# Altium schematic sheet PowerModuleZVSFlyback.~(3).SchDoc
size 431 x 279 mm; Date: Not shown in title block; ApprovedBy: Not shown in title block; CheckedBy: Not shown in title block; Author: Not shown in title block; CompanyName: Not shown in title block; Engineer: Not shown in title block; Organization: Not shown in title block; Address1: Not shown in title block; Address2: Not shown in title block; Address3: Not shown in title block; Address4: Not shown in title block; DocumentNumber: 1; Revision: Use project parameter SCH_Rev; SheetNumber: 3; SheetTotal: 3; PageSetup: Record=PageOptions¦CenterHorizontal=True¦CenterVertical=True¦PrintScale=1.00¦XCorrection=1.00¦YCorrection=1.00¦PrintKind=0¦BorderSize=5000000¦LeftOffset=0¦BottomOffset=0¦Orientation=2¦PaperLength=1000¦PaperWidth=1000¦Scale=100¦PaperSource=15¦PrintQuality=600¦MediaType=1¦DitherType=10¦PaperKind=Letter¦PrintScaleMode=1
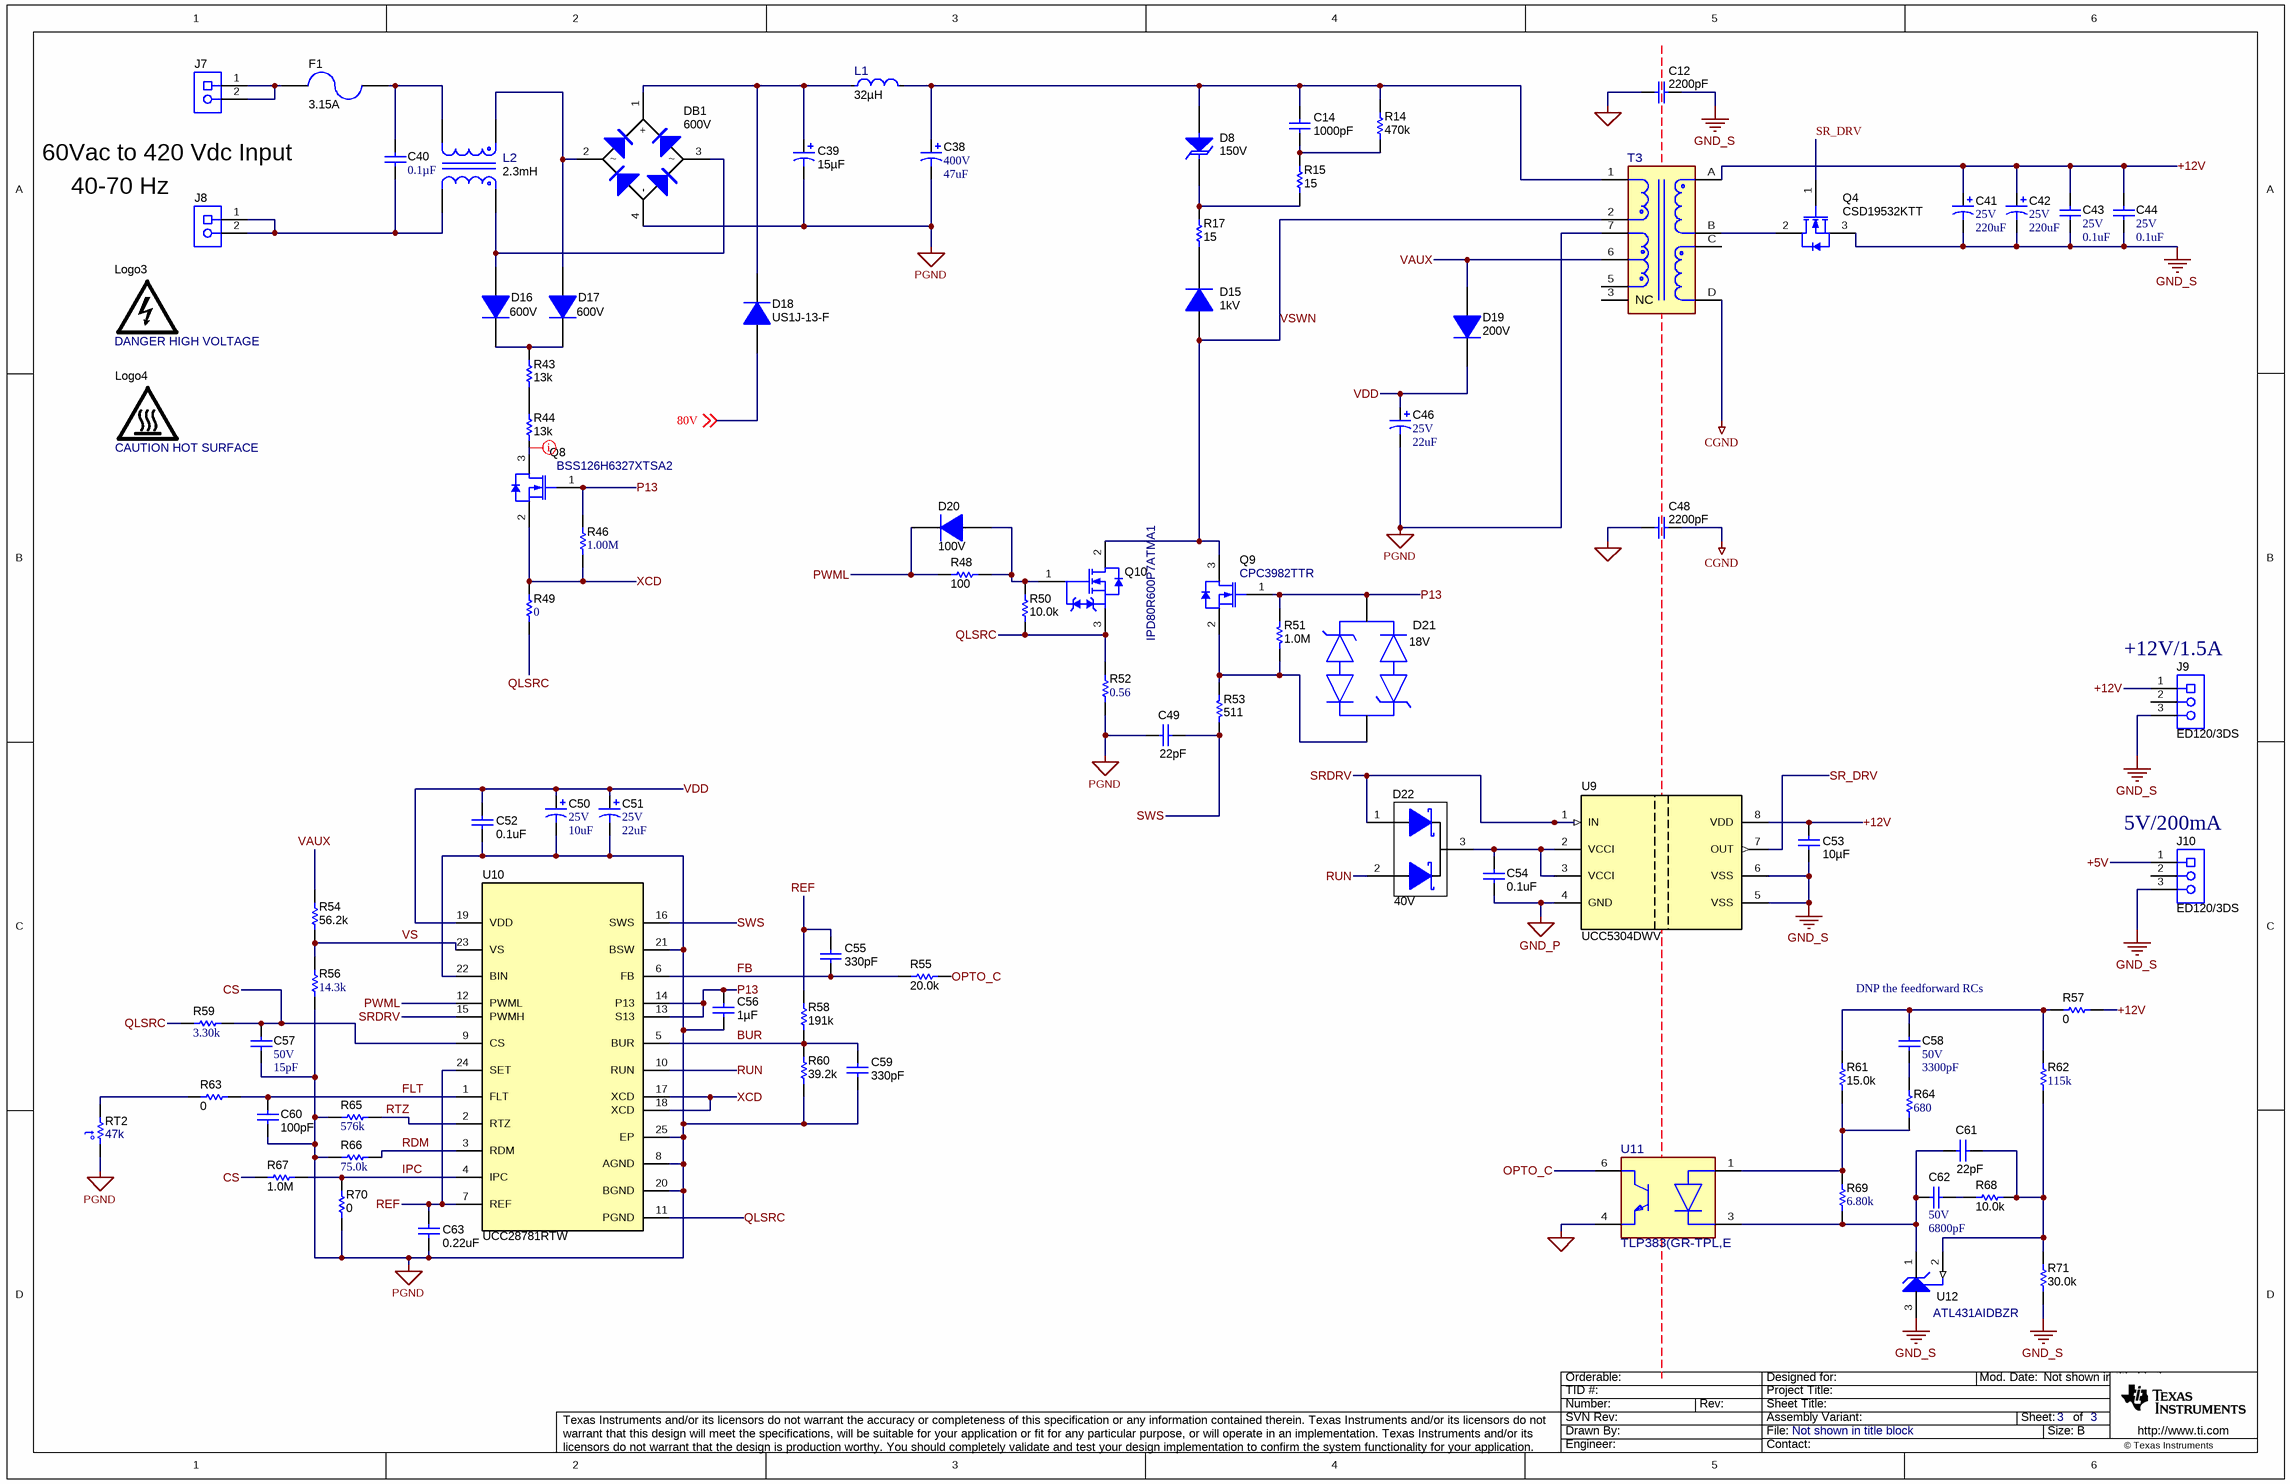
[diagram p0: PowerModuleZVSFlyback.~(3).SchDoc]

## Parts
C12  ValueDisplayed: 2200pF  [C900_9x13]  (hidden comment: C921U222MVVDBA7317)
C14  ValueDisplayed: 1000pF  [1206L]  (hidden comment: GRM31BR72J102KW01L)
C38  VDC_V: 400V  ValueDisplayed: 47uF  [CAPPR7.5-16x25]  (hidden comment: UCS2G470MHD)
C39  ValueDisplayed: 15µF  [UVC_1000x1600]  (hidden comment: UVC2G150MPD)
C40  ValueDisplayed: 0.1µF  [B32933_600x1500x2650]  (hidden comment: B32933A3104K000)
C41  VDC_V: 25V  ValueDisplayed: 220uF  [BT_1000x1250]  (hidden comment: UBT1E221MPD1TD)
C42  VDC_V: 25V  ValueDisplayed: 220uF  [BT_1000x1250]  (hidden comment: UBT1E221MPD1TD)
C43  VDC_V: 25V  ValueDisplayed: 0.1uF  [0603]  (hidden comment: 06033D104KAT2A)
C44  VDC_V: 25V  ValueDisplayed: 0.1uF  [0603]  (hidden comment: 06033D104KAT2A)
C46  VDC_V: 25V  ValueDisplayed: 22uF  [SM_RADIAL_D]  (hidden comment: EEE-FC1E220P)
C48  ValueDisplayed: 2200pF  [C900_9x13]  (hidden comment: C921U222MVVDBA7317)
C49  ValueDisplayed: 22pF  [0402S]  (hidden comment: GCM1555C1H220JA16D)
C50  VDC_V: 25V  ValueDisplayed: 10uF  [CAPSMT_62_D55]  (hidden comment: EMVA250ADA100MD55G)
C51  VDC_V: 25V  ValueDisplayed: 22uF  [SM_RADIAL_D]  (hidden comment: EEE-FC1E220P)
C52  ValueDisplayed: 0.1uF  [0402S]  (hidden comment: GRM155R71H104ME14D)
C53  ValueDisplayed: 10µF  [1206_180L]  (hidden comment: C1206C106J3RACAUTO)
C54  ValueDisplayed: 0.1uF  [0402S]  (hidden comment: GRM155R71H104ME14D)
C55  ValueDisplayed: 330pF  [0402S]  (hidden comment: GRM155R71H331KA01D)
C56  Cap_F: 1µF  [0603S]  (hidden comment: CGA3E1X7R1V105K080AC)
C57  VDC_V: 50V  ValueDisplayed: 15pF  [0402]  (hidden comment: CC0402JRNPO9BN150)
C58  VDC_V: 50V  ValueDisplayed: 3300pF  [0402]  (hidden comment: GRM155R71H332KA01D)
C59  ValueDisplayed: 330pF  [0402S]  (hidden comment: GRM155R71H331KA01D)
C60  ValueDisplayed: 100pF  [0402S]  (hidden comment: GRM1555C1H101JA01D)
C61  ValueDisplayed: 22pF  [0402S]  (hidden comment: GCM1555C1H220JA16D)
C62  VDC_V: 50V  ValueDisplayed: 6800pF  [0402]  (hidden comment: GRM155R71H682KA88D)
C63  ValueDisplayed: 0.22uF  [0402S]  (hidden comment: GRM155R71C224KA12D)
D8  VRWM: 150V  [SMA]  (hidden comment: SMAJ150A)
D15  Vr_V: 1kV  [SMA]  (hidden comment: MRA4007T3G)
D16  Vr_V: 600V  [TUMD2SM]  (hidden comment: RFU02VSM6STR)
D17  Vr_V: 600V  [TUMD2SM]  (hidden comment: RFU02VSM6STR)
D18  US1J-13-F  [SMA]
D19  Vr_V: 200V  [SOD-123H]  (hidden comment: CSFMT104-HF)
D20  Vr_V: 100V  [SOD-323]  (hidden comment: BAS316,115)
D21  CDSOD323-T18C  [FP-CDSOD323-T18C_SOD323-MFG]  (value not drawn)
D22  Vr_V: 40V  [SOT-323]  (hidden comment: BAS40W-05-7-F)
DB1  value 600V  [Z4-D]  (hidden comment: Z4DGP406L-HF)
F1  Irating_A: 3.15A  [FUSE_392]  (hidden comment: 39213150000)
J7  ED120/2DS  [On-Shore_ED120_2DS]  (value not drawn)
J8  ED120/2DS  [On-Shore_ED120_2DS]  (value not drawn)
J9  ED120/3DS  [On-Shore_ED120_3DS]
J10  ED120/3DS  [On-Shore_ED120_3DS]
L1  Ind_H: 32µH  [FP-7447052_PTH_D10MM0-MFG]  (hidden comment: 7447052)
L2  Ind_H: 2.3mH  [FP-RLTI-1387_PTH_CMC_0IN38_0IN60-MFG]  (hidden comment: RLTI-1387)
Logo3  DANGER HIGH VOLTAGE  [IEC_HighVoltage_Small]  (no BOM)
Logo4  CAUTION HOT SURFACE  [IEC_HotSurface_Small]  (no BOM)
Q4  CSD19532KTT  [KTT0002A]
Q8  BSS126H6327XTSA2  [SOT-23L]
Q9  CPC3982TTR  [SOT-23L]
Q10  IPD80R600P7ATMA1  [DPAK]
R14  ValueDisplayed: 470k  [0805_HV1]  (hidden comment: CRCW0805470KJNEA)
R15  ValueDisplayed: 15  [0805_HV1]  (hidden comment: CRCW080515R0JNEA)
R17  ValueDisplayed: 15  [0805_HV1]  (hidden comment: CRCW080515R0JNEA)
R43  ValueDisplayed: 13k  [1206L]  (hidden comment: CRCW120613K0JNEA)
R44  ValueDisplayed: 13k  [1206L]  (hidden comment: CRCW120613K0JNEA)
R46  ValueDisplayed: 1.00M  [0603]  (hidden comment: MCT06030C1004FP500)
R48  ValueDisplayed: 100  [0805_HV1]  (hidden comment: CRCW0805100RJNEA)
R49  ValueDisplayed: 0  [0603]  (hidden comment: RC0603JR-070RL)
R50  ValueDisplayed: 10.0k  [0402S]  (hidden comment: CRCW040210K0FKED)
R51  ValueDisplayed: 1.0M  [0402S]  (hidden comment: CRCW04021M00JNED)
R52  ValueDisplayed: 0.56  [1206]  (hidden comment: ERJ-8RQFR56V)
R53  ValueDisplayed: 511  [0402S]  (hidden comment: CRCW0402511RFKED)
R54  ValueDisplayed: 56.2k  [0402S]  (hidden comment: CRCW040256K2FKED)
R55  ValueDisplayed: 20.0k  [0402S]  (hidden comment: CRCW040220K0FKED)
R56  ValueDisplayed: 14.3k  [0402]  (hidden comment: CRCW040214K3FKED)
R57  ValueDisplayed: 0  [0402S]  (hidden comment: RC0402JR-070RL)
R58  ValueDisplayed: 191k  [0402S]  (hidden comment: CRCW0402191KFKED)
R59  ValueDisplayed: 3.30k  [0402]  (hidden comment: RK73H1ETTP3301F)
R60  ValueDisplayed: 39.2k  [0402S]  (hidden comment: CRCW040239K2FKED)
R61  ValueDisplayed: 15.0k  [0402S]  (hidden comment: CRCW040215K0FKED)
R62  ValueDisplayed: 115k  [0402]  (hidden comment: RC1005F1153CS)
R63  ValueDisplayed: 0  [0402S]  (hidden comment: CRCW04020000Z0EDHP)
R64  ValueDisplayed: 680  [0603]  (hidden comment: RC0603FR-07680RL)
R65  ValueDisplayed: 576k  [0402]  (hidden comment: CRCW0402576KFKED)
R66  ValueDisplayed: 75.0k  [0402]  (hidden comment: CRCW040275K0FKED)
R67  ValueDisplayed: 1.0M  [0402S]  (hidden comment: CRCW04021M00JNED)
R68  ValueDisplayed: 10.0k  [0402S]  (hidden comment: CRCW040210K0FKED)
R69  ValueDisplayed: 6.80k  [0603]  (hidden comment: RC0603FR-076K8L)
R70  ValueDisplayed: 0  [0402S]  (hidden comment: CRCW04020000Z0EDHP)
R71  ValueDisplayed: 30.0k  [0402S]  (hidden comment: CRCW040230K0FKED)
RT2  value 47k  [0603S]  (hidden comment: NCP18WB473J03RB)
T3  RLTI-1324  [FP-RLTI-1324_PTH_0IN980_0IN766-MFG]  (value not drawn)
U9  UCC5304DWV  [DWV0008A]
U10  UCC28781RTW  [RTW0024B]
U11  TLP383(GR-TPL,E  [FP-TLP383(GR-TPL,E_SO6-4-MFG]
U12  ATL431AIDBZR  [DBZ0003A_L]

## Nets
CGND: C48.1 T3.D
GND2: C12.2 C48.2 U11.4(Emitter)
GND_P: C54.2 U9.4(GND)
GND_S: C12.1 C41.2(-) C42.2(-) C43.2 C44.2 C53.2 J9.3 J10.3 Q4.3(S) R71.2 U9.5(VSS) U9.6(VSS) U12.3(ANODE)
PGND: C38.2(-) C39.2(-) C46.2(-) C49.1 C50.2(-) C51.2(-) C52.2 C56.2 C57.2 C59.2 C60.1 C63.2 DB1.4(-) R52.1 R56.1 R60.2 R65.1 R66.1 R70.1 RT2.2 T3.7 U10.8(AGND) U10.20(BGND) U10.21(BSW) U10.22(BIN) U10.25(EP)
80V: D18.2(A) ; off-sheet 80V
+5V: J10.1
+12V: C41.1(+) C42.1(+) C43.1 C44.1 C53.1 J9.1 R57.1 T3.A U9.8(VDD)
BUR: C59.1 R58.2 R60.1 U10.5(BUR)
CS: C57.1 R59.2 R67.2 U10.9(CS)
FB: C55.2 R55.1 U10.6(FB)
FLT: C60.2 R63.2 U10.1(FLT)
IPC: R67.1 R70.2 U10.4(IPC)
OPTO_C: R55.2 U11.6(Collector)
P13: C56.1 D21.2 Q8.1(G) Q9.1(G) R46.2 R51.2 U10.13(S13) U10.14(P13)
PWML: D20.1(K) R48.1 U10.12(PWML)
QLSRC: Q10.3(S) R49.1 R50.1 R52.2 R59.1 U10.11(PGND)
RDM: R66.2 U10.3(RDM)
REF: C55.1 C63.1 R58.1 U10.7(REF) U10.24(SET)
RTZ: R65.2 U10.2(RTZ)
RUN: D22.2(A) U10.10(RUN)
SR_DRV: Q4.1(G) U9.7(OUT)
SRDRV: D22.1(A) U9.1(IN) U10.15(PWMH)
SWS: C49.2 R53.1 U10.16(SWS)
VAUX: D19.2(A) R54.1 T3.6
VDD: C46.1(+) C50.1(+) C51.1(+) C52.1 D19.1(K) U10.19(VDD)
VS: R54.2 R56.2 U10.23(VS)
VSWN: D15.2(A) Q9.3(D) Q10.2(D) T3.2
XCD: Q8.2(S) R46.1 R49.2 U10.17(XCD) U10.18(XCD)
NetC14_1: C14.1 C38.1(+) D8.2(A) L1.2 R14.2 T3.1
NetC14_2: C14.2 R14.1 R15.2
NetC39_1: C39.1(+) D18.1(K) DB1.1(+) L1.1
NetC40_1: C40.1 F1.1 L2.3
NetC40_2: C40.2 J8.1 J8.2 L2.2
NetC54_1: C54.1 D22.3(K) U9.2(VCCI) U9.3(VCCI)
NetC58_1: C58.1 R57.2 R61.2 R62.2
NetC58_2: C58.2 R64.2
NetC61_1: C61.1 C62.2 R69.1 U11.3(Cathode) U12.1(CATHODE)
NetC61_2: C61.2 R62.1 R68.2 R71.1 U12.2(REF)
NetC62_1: C62.1 R68.1
NetD8_1: D8.1(K) R15.1 R17.2
NetD15_1: D15.1(K) R17.1
NetD16_1: D16.1(K) D17.1(K) R43.1
NetD16_2: D16.2(A) DB1.3 L2.1
NetD17_2: D17.2(A) DB1.2 L2.4
NetD20_2: D20.2(A) Q10.1(G) R48.2 R50.2
NetD21_1: D21.1 Q9.2(S) R51.1 R53.2
NetF1_2: F1.2 J7.1 J7.2
NetQ4_2: Q4.2(D) T3.B
NetQ8_3: Q8.3(D) R44.2
NetR43_2: R43.2 R44.1
NetR61_1: R61.1 R64.1 R69.2 U11.1(Anode)
NetR63_1: R63.1 RT2.1

Not connected (* = marked no-connect by the designer): J9 2; J10 2; T3 3(NC) 5 C

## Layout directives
net class HV: NetQ8_3

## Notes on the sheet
- 60Vac to 420 Vdc Input
- 40-70 Hz
- (near D21) 18V
- (near J9) +12V/1.5A
- (near J10) 5V/200mA
- (near C58) DNP the feedforward RCs

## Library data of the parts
C12 C48 = CMP-0078358-1: CAP, CERM, 2200 pF, X1 400 VAC/Y1 400 VAC, +/- 20%, Y5V, D9xL13mm; Manufacturer: Kemet; Cap_F: 2.2nF; SizeAreaWB_mm2: 121; VAC_X: 400V; SizeArea_mm2: 81; AEC Qualified: N; AEC Category: Q200; Value: 2200pF; TaMax_C: 125°C; SizeZ_mm: 13; TaMin_C: -40°C; SizeY_mm: 9; U/M: EA; AC_Safety: X1Y1; Cap_Case: 9x13mm
C14 = CMP-0008909-2: CAP, CERM, 1000 pF, 630 V, +/- 10%, X7R, 1206; Manufacturer: MuRata; TaMin_C: -55°C; Polarized: N; SizeAreaWB_mm2: 10.92; Value1: Unknown; U/M: EA; Value: 1000pF; TaMax_C: 125°C; SizeZ_mm: 1.35; SizeX_mm: 3.2; SizeY_mm: 1.6; Cap_Case: 1206; Value2: 630V; SizeArea_mm2: 5.12; Cap_F: 1nF; AEC Category: Q200
C38 = CMP-0010241-2: CAP, AL, 47 uF, 400 V, +/- 20%, TH; Manufacturer: Nichicon; TaMin_C: -40°C; Polarized: Y; SizeAreaWB_mm2: 324; Value1: Unknown; U/M: EA; Value: 47uF; TaMax_C: 105°C; SizeZ_mm: 25; SizeX_mm: 16; Cap_Case: Radial  16x25mm; SizeArea_mm2: 256; CompType: Capacitor; AEC Qualified: N; Cap_F: 47µF; IRMS_A: 1.18A; AEC Category: Q200
C39 = CMP-0860955-2: CAP, AL, 15 µF, 400 V, +/- 20%, AEC-Q200 Grade 2, TH; Manufacturer: Nichicon; SizeArea_mm2: 100; CompType: Capacitor; Value2: 400V; SizeZ_mm: 18; IRMS_A: 180mA; Polarized: Y; SizeX_mm: 10; Value: 15uF; TaMin_C: -40°C; AEC Grade: 2; U/M: EA; SizeAreaWB_mm2: 144; Cap_Case: 10x16; TaMax_C: 105°C; AEC Category: Q200
C40 = CMP-0077664-2: CAP, Film, 0.1 µF, X2 305 VAC, +/- 10%, AEC-Q200 Grade 2, TH; Manufacturer: TDK; TaMin_C: -40°C; Polarized: N; SizeAreaWB_mm2: 210.0; Value: 0.1uF; TaMax_C: 105°C; VAC_X: 305; SizeZ_mm: 15.0; SizeX_mm: 26.0; SizeY_mm: 5.5; SizeArea_mm2: 143.0; AEC Qualified: Y; Cap_F: 100nF; AEC Grade: 2; AEC Category: Q200
C41 C42 = CMP-0010527-1: CAP, AL, 220 uF, 25 V, +/- 20%, 0.1 ohm, TH; Manufacturer: Nichicon; TaMin_C: -40°C; ESR_ohm: 1d; Polarized: Y; SizeAreaWB_mm2: 144; Value1: 0.1 ohm; U/M: EA; Value: 220uF; TaMax_C: 125°C; SizeZ_mm: 14.5; SizeX_mm: 10; Cap_Case: 10x12.5mm; SizeArea_mm2: 100; CompType: Capacitor; Cap_F: 220µF; IRMS_A: 6.8dA; AEC Category: Q200
C43 C44 = CMP-0006758-5: CAP, CERM, 0.1 uF, 25 V, +/- 10%, X5R, 0603; Manufacturer: AVX; TaMin_C: -55°C; ESR_ohm: 0.048; Polarized: N; SizeAreaWB_mm2: 4.68; Value1: 0.048 ohm; U/M: EA; Value: 0.1uF; TaMax_C: 85°C; SizeZ_mm: 1; SizeX_mm: 1.6; SizeY_mm: 0.8; SizeArea_mm2: 1.28; Cap_F: 100nF; IRMS_A: 5.3dA; AEC Category: Q200
C46 C51 = CMP-0010654-1: CAP, AL, 22 uF, 25 V, +/- 20%, 1 ohm, SMD; Manufacturer: Panasonic; TaMin_C: -40°C; ESR_ohm: 1; Polarized: Y; SizeAreaWB_mm2: 84.28; Value1: 1 ohm; U/M: EA; Value: 22uF; TaMax_C: 105°C; SizeZ_mm: 5.4; SizeX_mm: 7.8; SizeY_mm: 6.6; Cap_Case: D; SizeArea_mm2: 51.48; CompType: Capacitor; Cap_F: 22µF; IRMS_A: 1.15dA; AEC Category: Q200
C49 C61 = CMP-0006348-2: CAP, CERM, 22 pF, 50 V, +/- 5%, C0G/NP0, AEC-Q200 Grade 1, 0402; Manufacturer: MuRata; TaMin_C: -55°C; Polarized: N; SizeAreaWB_mm2: 3; Value1: Unknown; U/M: EA; Value: 22pF; TaMax_C: 125°C; SizeZ_mm: 0.6; SizeX_mm: 1; SizeY_mm: 0.5; Cap_Case: 0402; Value2: 50V; AEC Qualified: Y; AEC Category: Q200
C50 = CMP-0010785-1: CAP, AL, 10 uF, 25 V, +/- 20%, SMD; Manufacturer: Chemi-Con; TaMin_C: -40°C; Polarized: Y; SizeAreaWB_mm2: 28.09; Value1: Unknown; U/M: EA; Value: 10uF; TaMax_C: 85°C; SizeZ_mm: 5.2; SizeX_mm: 4.3; Cap_Case: D55; SizeArea_mm2: 18.49; CompType: Capacitor; Cap_F: 10µF; IRMS_A: 24mA; AEC Category: Q200
C52 C54 = CMP-0006675-2: CAP, CERM, 0.1 uF, 50 V, +/- 20%, X7R, 0402; Manufacturer: MuRata; TaMin_C: -55°C; Polarized: N; SizeAreaWB_mm2: 3; Value1: Unknown; U/M: EA; Value: 0.1uF; TaMax_C: 125°C; SizeZ_mm: 0.6; SizeX_mm: 1; SizeY_mm: 0.5; Cap_Case: 0402; Value2: 50V; Cap_F: 100nF; AEC Category: Q200
C53 = CMP-0081062-1: CAP, CERM, 10 µF, 25 V,+/- 5%, X7R, AEC-Q200 Grade 1, 1206; Manufacturer: Kemet; TaMin_C: -55°C; Polarized: N; SizeAreaWB_mm2: 10.92; U/M: EA; Value: 10uF; TaMax_C: 125°C; SizeZ_mm: 1.8; SizeX_mm: 3.2; SizeY_mm: 1.6; Cap_Case: 1206_180; Value2: 25V; SizeArea_mm2: 5.12; AEC Qualified: Y; AEC Grade: 1; AEC Category: Q200
C55 C59 = CMP-0006687-2: CAP, CERM, 330 pF, 50 V, +/- 10%, X7R, 0402; Manufacturer: MuRata; TaMin_C: -55°C; Polarized: N; SizeAreaWB_mm2: 3; Value1: Unknown; U/M: EA; Value: 330pF; TaMax_C: 125°C; SizeZ_mm: 0.6; SizeX_mm: 1; SizeY_mm: 0.5; Cap_Case: 0402; Value2: 50V; AEC Category: Q200
C56 = CMP-0007067-4: CAP, CERM, 1 uF, 35 V, +/- 10%, X7R, AEC-Q200 Grade 1, 0603; Manufacturer: TDK; TaMin_C: -55°C; ESR_ohm: 5.522m; Polarized: N; SizeAreaWB_mm2: 4.68; Value1: 0.005522 ohm; U/M: EA; Value: 1uF; TaMax_C: 125°C; SizeZ_mm: 1; SizeX_mm: 1.6; SizeY_mm: 0.8; Cap_Case: 0603; Value2: 35V; SizeArea_mm2: 1.28; AEC Qualified: Y; IRMS_A: 2.21617A; AEC Category: Q200
C57 = CMP-0006304-2: CAP, CERM, 15 pF, 50 V, +/- 5%, C0G/NP0, 0402; Manufacturer: Yageo America; TaMin_C: -55°C; Polarized: N; SizeAreaWB_mm2: 3; Value1: Unknown; U/M: EA; Value: 15pF; TaMax_C: 125°C; SizeZ_mm: 0.6; SizeX_mm: 1; SizeY_mm: 0.5; AEC Category: Q200
C58 = CMP-0006688-2: CAP, CERM, 3300 pF, 50 V, +/- 10%, X7R, 0402; Manufacturer: MuRata; TaMin_C: -55°C; Polarized: N; SizeAreaWB_mm2: 3; Value1: Unknown; U/M: EA; Value: 3300pF; TaMax_C: 125°C; SizeZ_mm: 0.6; SizeX_mm: 1; SizeY_mm: 0.5; Cap_F: 3.3nF; AEC Category: Q200
C60 = CMP-0006410-2: CAP, CERM, 100 pF, 50 V, +/- 5%, C0G/NP0, 0402; Manufacturer: MuRata; TaMin_C: -55°C; Polarized: N; SizeAreaWB_mm2: 3; Value1: Unknown; U/M: EA; Value: 100pF; TaMax_C: 125°C; SizeZ_mm: 0.6; SizeX_mm: 1; SizeY_mm: 0.5; Cap_Case: 0402; Value2: 50V; AEC Category: Q200
C62 = CMP-0006696-2: CAP, CERM, 6800 pF, 50 V, +/- 10%, X7R, 0402; Manufacturer: MuRata; TaMin_C: -55°C; Polarized: N; SizeAreaWB_mm2: 3; Value1: Unknown; U/M: EA; Value: 6800pF; TaMax_C: 125°C; SizeZ_mm: 0.6; SizeX_mm: 1; SizeY_mm: 0.5; Cap_F: 6.8nF; AEC Category: Q200
C63 = CMP-0006648-2: CAP, CERM, 0.22 uF, 16 V, +/- 10%, X7R, 0402; Manufacturer: MuRata; TaMin_C: -55°C; Polarized: N; SizeAreaWB_mm2: 3; Value1: Unknown; U/M: EA; Value: 0.22uF; TaMax_C: 125°C; SizeZ_mm: 0.6; SizeX_mm: 1; SizeY_mm: 0.5; Cap_Case: 0402; Value2: 16V; Cap_F: 220nF; AEC Category: Q200
D8 = CMP-0084982-1: Diode, TVS, Uni, 150 V, 243 Vc, 400 W, 1.6 A, SMA; Manufacturer: Littelfuse; Vc: 243V; Ipp: 1.6A; RJA_CperW: 120; AEC Qualified: N; Value: 150V; Ppk: 400W; AEC Category: Q101; SizeArea_mm2: 16.3228; SizeAreaWB_mm2: 37.3428; SizeZ_mm: 2.87; Vbr_Max: 185V; SizeX_mm: 5.59; SizeY_mm: 2.92; Vbr_Min: 167V
D15 = CMP-0077082-2: Diode, Standard Recovery Rectifier, 1000 V, 1 A, AEC-Q101, SMA; Manufacturer: ON Semiconductor; SizeAreaWB_mm2: 37.3428; SizeArea_mm2: 16.3228; AEC Qualified: Y; TJmax_C: 175°C; AEC Category: Q101; Value: 1000V; SizeZ_mm: 2.87; Green_REACh: Passed; Io_A: 1A; Vf_V: 1.1V; SizeY_mm: 2.92; Green_Lifecycle: Active; SizeX_mm: 5.59; RJC_CperW: 16.2
D16 D17 = CMP-0080762-2: Diode, Standard Recovery Rectifier, 600 V, 0.2 A, 2x1.4mm; Manufacturer: Rohm; SizeArea_mm2: 3.5; AEC Qualified: N; SizeY_mm: 1.4; Io_A: 200mA; SizeZ_mm: 0.8; Vf_V: 2.2V; SizeAreaWB_mm2: 8.4; TJmax_C: 150°C; Value1: 0.2A; SizeX_mm: 2.5; AEC Category: Q101; Value: 600V
D18 = CMP-0077027-2: Diode, Ultrafast, 600 V, 1 A, SMA; Manufacturer: Diodes Inc.; Value: 600V; TJmax_C: 150°C; Value1: 1A; Value2: 1.7V; SizeY_mm: 2.92; Green_REACh: Passed; Green_Lifecycle: Active; SizeX_mm: 5.59; AEC Category: Q101; SizeAreaWB_mm2: 37.3428; SizeZ_mm: 2.87; SizeArea_mm2: 16.3228
D19 = CMP-0029199-2: Diode, Superfast Rectifier, 200 V, 1 A, 3.5x1.6mm; Manufacturer: Comchip Technology; Vf_V: 950mV; Value: 200V; Value1: 1A; Value2: 0.95V; TJmax_C: 150°C; SizeAreaWB_mm2: 11.7; SizeArea_mm2: 5.6; SizeX_mm: 3.5; SizeY_mm: 1.6; SizeZ_mm: 1; AEC Category: Q101; AEC Qualified: N
D20 = CMP-0029006-2: Diode, Ultrafast, 100 V, 0.25 A, SOD-323; Manufacturer: Nexperia; SizeY_mm: 1.35; Value1: 0.25A; SizeAreaWB_mm2: 8.695; SizeZ_mm: 1; Io_A: 250mA; Value2: 1.4V; SizeX_mm: 2.7; Green_REACh: Incomplete; TJmax_C: 150°C; Green_Lifecycle: Not Set; AEC Category: Q101; Value: 100V; SizeArea_mm2: 3.645
D21 = CMP-0087587-1: Diode, TVS, Bi, 18 V, SOD-323; Manufacturer: Bourns Inc.; SizeZ_mm: 1.14mm; AEC Qualified: No
D22 = CMP-0028437-2: Diode, Schottky, 40 V, 0.2 A, SOT-323; Manufacturer: Diodes Inc.; Io_A: 200mA; Green_Lifecycle: Not Set; SizeAreaWB_mm2: 10.24; Green_REACh: Incomplete; Value1: 0.2A; Value: 40V; SizeZ_mm: 1.1; SizeX_mm: 2.2; Vf_V: 800mV; Value2: 0.8V; SizeArea_mm2: 4.84; AEC Category: Q101
DB1 = Z4DGP406L-HF: Diode, P-N-Bridge, 600 V, 4 A, Z4-D; Manufacturer: Comchip Technology; U/M: EA; Vf_V: 0.95; Value1: 4A; Value2: 0.95V; Io_A: 4; Vr_V: 600; TJmax_C: 175; SizeAreaWB_mm2: 126.25; SizeArea_mm2: 85.05; SizeX_mm: 10.5; SizeY_mm: 8.1; SizeZ_mm: 1.55; AEC Category: Q101; AEC Qualified: N; Green_Lifecycle: Not Set; Green_REACh: Incomplete
F1 = CMP-0003561-2: Fuse, 3.15 A, 250VAC/VDC, TH; Manufacturer: Littelfuse; VAC_V: 250V
J7 J8 = CMP-0074910-1: Terminal Block, 5.08 mm, 2x1, Brass, TH; Manufacturer: On-Shore Technology; Pitch_mm: 5.08; Gender: Female; Shrouded: N; Row_Count: 1; Current_A: 15A; Voltage_V: 300V; Cert_CULUS: Y; CNHeader: False; CT: True; Green_Lifecycle: Not Set; Green_REACh: Incomplete
J9 J10 = CMP-0074911-1: Terminal Block, 5.08 mm, 3x1, Brass, TH; Manufacturer: On-Shore Technology; Cert_VDE: Y; CNHeader: False; Current_A: 15A; Green_Lifecycle: Not Set; Shrouded: N; Gender: Female; Green_REACh: Incomplete; Voltage_V: 300V; Row_Count: 1; Pitch_mm: 5.08; CT: True
L1 = CMP-0087546-1: WE-FI Leaded Toroidal Line Choke; Manufacturer: Wurth; SizeZ_mm: 10mm; Irms: 2.6A; DCR_ohm: 0.045; AEC Qualified: No; Symbol Name: SYM-7447052
L2 = CMP-0092946-1: Common Mode Choke, 2.3mH 35%, 0.6x0.38x0.75 IN; Manufacturer: Renco; Test Frequency: 10kHz; SizeZ_mm: 0.75inch; DCR_ohm: 0.03; AEC Qualified: No
Logo3 = CMP-0074835-1: IEC 61010-1 High Voltage Warning; SymbolCreator: a0412235
Logo4 = CMP-0074837-1: IEC 61010-1 Hot Surface Warning; SymbolCreator: a0412235
Q4 = CMP-0000957-3: MOSFET, N-CH, 100 V, 136 A, KTT0002A (TO-263-2); Alternate Manufacturer: None; Manufacturer: Texas Instruments; SizeZ_mm: 4.7; ChType: N; Value2: 44 nC; VdsMax_V: 100V; SizeX_mm: 14.3; SizeAreaWB_mm2: 198.208; SizeY_mm: 10.16; Vgs_V: 20V; QgTyp_nC: 44; Value: 100V; SizeArea_mm2: 145.288; AEC Category: Q101; IdsMax_A: 136A
Q8 = CMP-0067574-2: MOSFET, N-CH, Depletion Mode, 100 V, 0.17 A, AEC-Q101, SOT-23; Manufacturer: Infineon Technologies; Alternate Manufacturer: None; ChType: N; Value: 600V; Value1: ? ohm; Value2: 1.4 nC; QgTyp_nC: 1.4; Vgs_V: 20V; IdsMax_A: 21mA; SizeAreaWB_mm2: 14.0; SizeArea_mm2: 7.5; SizeX_mm: 2.5; SizeY_mm: 3.0; SizeZ_mm: 1.1; AEC Category: Q101; AEC Qualified: Y
Q9 = CMP-0081263-2: MOSFET, N-CH, Depletion Mode, 800 V, SOT-23; Alternate Manufacturer: None; Manufacturer: IXYS; SizeAreaWB_mm2: 14; Vgs_V: 15V; Value1: ? ohm; VdsMax_V: 800V; Value: 800V; SizeZ_mm: 1.1; SizeX_mm: 2.5; SizeY_mm: 3; Value2: ? nC; SizeArea_mm2: 7.5; ChType: N; AEC Category: Q101
Q10 = CMP-0083711-2: MOSFET, N-CH, 800 V, 8 A, DPAK; Manufacturer: Infineon Technologies; Alternate Manufacturer: None; AEC Qualified: N; Vgs_V: 20V; SizeY_mm: 6.54; VdsMax_V: 800V; IdsMax_A: 8A; SizeX_mm: 9.91; Value2: 20 nC; AEC Category: Q101; ChMode: Enhancement; SizeAreaWB_mm2: 101.7114; Value1: ? ohm; SizeArea_mm2: 64.8114; Value: 800V; SizeZ_mm: 2.29; QgTyp_nC: 20
R14 = CMP-0020554-3: RES, 470 k, 5%, 0.125 W, AEC-Q200 Grade 0, 0805; Manufacturer: Vishay-Dale; Power_W: 125mW; TempCo: 200 ppm/C; Value: 470k; EIA_Code: E24; SizeX_mm: 2; SizeY_mm: 1.25; SizeZ_mm: 1.45; Value2: 0.125W; SizeArea_mm2: 2.5; AEC Qualified: Y; VDC_V: 150V; AEC Category: Q200; AEC Grade: 0
R15 R17 = CMP-0020464-3: RES, 15, 5%, 0.125 W, AEC-Q200 Grade 0, 0805; Manufacturer: Vishay-Dale; Power_W: 125mW; TempCo: 200 ppm/C; Value_Code: 15R0; Value: 15; EIA_Code: E24; SizeX_mm: 2; SizeY_mm: 1.25; SizeZ_mm: 1.45; Value2: 0.125W; SizeArea_mm2: 2.5; AEC Qualified: Y; VDC_V: 150V; AEC Category: Q200; AEC Grade: 0
R43 R44 = CMP-0018589-3: RES, 13 k, 5%, 0.25 W, AEC-Q200 Grade 0, 1206; Manufacturer: Vishay-Dale; Power_W: 250mW; TempCo: 200 ppm/C; Value_Code: 13k0; Value: 13k; EIA_Code: E24; SizeX_mm: 3.2; SizeY_mm: 1.6; SizeZ_mm: 1.35; Value2: 0.25W; SizeArea_mm2: 5.12; AEC Qualified: Y; VDC_V: 200V; AEC Category: Q200; AEC Grade: 0
R46 = CMP-0022731-2: RES, 1.00 M, 1%, 0.125 W, 0603; Manufacturer: Vishay/Beyschlag; Power_W: 125mW; TempCo: 50 ppm/C; Value_Code: 1M00; U/M: EA; Value: 1.00Meg; EIA_Code: E96; Res_ohm: 1M; SizeX_mm: 1.6; SizeY_mm: 0.8; SizeZ_mm: 1; Value2: 0.125W; SizeArea_mm2: 1.28; AEC Qualified: N; VDC_V: 75V; AEC Category: Q200
R48 = CMP-0020445-3: RES, 100, 5%, 0.125 W, AEC-Q200 Grade 0, 0805; Manufacturer: Vishay-Dale; Power_W: 125mW; TempCo: 200 ppm/C; Value_Code: 100R; Value: 100; EIA_Code: E24; SizeX_mm: 2; SizeY_mm: 1.25; SizeZ_mm: 1.45; Value2: 0.125W; SizeArea_mm2: 2.5; AEC Qualified: Y; VDC_V: 150V; AEC Category: Q200; AEC Grade: 0
R49 = CMP-0025885-5: RES, 0, 5%, 0.1 W, 0603; Manufacturer: Yageo; Power_W: 100mW; TempCo: 200 ppm/C; Value_Code: 0000; Value: 0; EIA_Code: E24; SizeX_mm: 1.6; SizeZ_mm: 1; Value2: 0.1W; SizeArea_mm2: 1.28; AEC Qualified: N; VDC_V: 75V; AEC Category: Q200; SizeY_mm: 0.8; SizeAreaWB_mm2: 4.68
R50 R68 = CMP-0025958-3: RES, 10.0 k, 1%, 0.063 W, AEC-Q200 Grade 0, 0402; Manufacturer: Vishay-Dale; Power_W: 63mW; TempCo: 100 ppm/C; Value_Code: 10k0; Value: 10.0k; EIA_Code: E96; Res_ohm: 10k; SizeX_mm: 1; SizeY_mm: 0.5; SizeZ_mm: 0.6; Value2: 0.063W; AEC Qualified: Y; VDC_V: 50V; AEC Category: Q200; AEC Grade: 0
R51 = CMP-0026859-2: RES, 1.0 M, 5%, 0.063 W, AEC-Q200 Grade 0, 0402; Manufacturer: Vishay-Dale; Value: 1.0Meg; Res_ohm: 1M; Value_Code: 1M00; Power_W: 63mW; Value2: 0.063W; VDC_V: 50V; TempCo: 200 ppm/C; SizeArea_mm2: 0.5; SizeX_mm: 1; SizeZ_mm: 0.6; EIA_Code: E24; AEC Category: Q200; AEC Qualified: Y; AEC Grade: 0
R52 = CMP-0017792-3: RES, 0.56, 1%, 0.25 W, AEC-Q200 Grade 0, 1206; Manufacturer: Panasonic; Power_W: 250mW; TempCo: 250 ppm/C; Value_Code: R560; Value: 0.56; EIA_Code: E96; SizeX_mm: 3.2; SizeY_mm: 1.6; SizeZ_mm: 1.35; Value2: 0.25W; SizeArea_mm2: 5.12; AEC Qualified: Y; AEC Category: Q200; AEC Grade: 0; SizeAreaWB_mm2: 10.92
R53 = CMP-0026436-2: RES, 511, 1%, 0.063 W, AEC-Q200 Grade 0, 0402; Manufacturer: Vishay-Dale; Power_W: 63mW; TempCo: 100 ppm/C; Value_Code: 511R; Value: 511; EIA_Code: E96; SizeX_mm: 1; SizeY_mm: 0.5; SizeZ_mm: 0.6; Value2: 0.063W; AEC Qualified: Y; VDC_V: 50V; AEC Category: Q200; AEC Grade: 0
R54 = CMP-0026453-2: RES, 56.2 k, 1%, 0.063 W, AEC-Q200 Grade 0, 0402; Manufacturer: Vishay-Dale; Power_W: 63mW; TempCo: 100 ppm/C; Value_Code: 56k2; Value: 56.2k; EIA_Code: E96; SizeX_mm: 1; SizeY_mm: 0.5; SizeZ_mm: 0.6; Value2: 0.063W; AEC Qualified: Y; VDC_V: 50V; AEC Category: Q200; AEC Grade: 0
R55 = CMP-0026162-2: RES, 20.0 k, 1%, 0.063 W, AEC-Q200 Grade 0, 0402; Manufacturer: Vishay-Dale; Power_W: 63mW; TempCo: 100 ppm/C; Value_Code: 20k0; Value: 20.0k; EIA_Code: E96; Res_ohm: 20k; SizeX_mm: 1; SizeY_mm: 0.5; SizeZ_mm: 0.6; Value2: 0.063W; AEC Qualified: Y; VDC_V: 50V; AEC Category: Q200; AEC Grade: 0
R56 = CMP-0026016-3: RES, 14.3 k, 1%, 0.063 W, AEC-Q200 Grade 0, 0402; Manufacturer: Vishay-Dale; Power_W: 63mW; TempCo: 100 ppm/C; Value_Code: 14k3; Value: 14.3k; EIA_Code: E96; SizeX_mm: 1; SizeY_mm: 0.5; SizeZ_mm: 0.6; Value2: 0.063W; AEC Qualified: Y; VDC_V: 50V; AEC Category: Q200; AEC Grade: 0
R57 = CMP-0027004-2: RES, 0, 5%, 0.063 W, 0402; Manufacturer: Yageo America; Power_W: 63mW; TempCo: 200 ppm/C; Value_Code: 0000; U/M: EA; Value: 0; EIA_Code: E24; SizeX_mm: 1; SizeY_mm: 0.5; SizeZ_mm: 0.6; Value2: 0.063W; VDC_V: 50V; AEC Category: Q200
R58 = CMP-0026063-3: RES, 191 k, 1%, 0.063 W, AEC-Q200 Grade 0, 0402; Manufacturer: Vishay-Dale; Power_W: 63mW; TempCo: 100 ppm/C; Value: 191k; EIA_Code: E96; SizeX_mm: 1; SizeY_mm: 0.5; SizeZ_mm: 0.6; Value2: 0.063W; AEC Qualified: Y; VDC_V: 50V; AEC Category: Q200; AEC Grade: 0
R59 = CMP-0026750-1: RES, 3.30 k, 1%, 0.063 W, AEC-Q200 Grade 0, 0402; Manufacturer: KOA Speer; Power_W: 63mW; TempCo: 100 ppm/C; Value_Code: 3k30; U/M: EA; Value: 3.30k; Res_ohm: 3.3k; SizeX_mm: 1; SizeY_mm: 0.5; SizeZ_mm: 0.6; Value2: 0.063W; AEC Qualified: Y; VDC_V: 50V; AEC Grade: 0; AEC Category: Q200
R60 = CMP-0026327-2: RES, 39.2 k, 1%, 0.063 W, AEC-Q200 Grade 0, 0402; Manufacturer: Vishay-Dale; Power_W: 63mW; TempCo: 100 ppm/C; Value_Code: 39k2; Value: 39.2k; EIA_Code: E96; SizeX_mm: 1; SizeY_mm: 0.5; SizeZ_mm: 0.6; Value2: 0.063W; AEC Qualified: Y; VDC_V: 50V; AEC Category: Q200; AEC Grade: 0
R61 = CMP-0026027-3: RES, 15.0 k, 1%, 0.063 W, AEC-Q200 Grade 0, 0402; Manufacturer: Vishay-Dale; Power_W: 63mW; TempCo: 100 ppm/C; Value_Code: 15k0; Value: 15.0k; EIA_Code: E96; Res_ohm: 15k; SizeX_mm: 1; SizeY_mm: 0.5; SizeZ_mm: 0.6; Value2: 0.063W; AEC Qualified: Y; VDC_V: 50V; AEC Category: Q200; AEC Grade: 0
R62 = CMP-0077547-1: RES, 115 k, 1%, 0.0625 W, 0402; Manufacturer: Samsung Electro-Mechanics; Power_W: 62.5mW; TempCo: 300 ppm/C; U/M: EA; Value: 115k; EIA_Code: E96; SizeX_mm: 1.0; SizeY_mm: 0.5; SizeZ_mm: 0.6; AEC Qualified: N; VDC_V: 50V; AEC Category: Q200
R63 R70 = CMP-0081856-1: RES, 0, 0%, 0.2 W, AEC-Q200 Grade 0, 0402; Manufacturer: Vishay-Dale; SizeAreaWB_mm2: 3; SizeArea_mm2: 0.5; AEC Qualified: Y; AEC Category: Q200; Value: 0; SizeZ_mm: 0.6; Power_W: 200mW; VDC_V: 50V; Value2: 0.2W; SizeX_mm: 1
R64 = CMP-0023235-5: RES, 680, 1%, 0.1 W, 0603; Manufacturer: Yageo; Power_W: 100mW; TempCo: 100 ppm/C; Value_Code: 680R; Value: 680; SizeX_mm: 1.6; SizeY_mm: 0.8; SizeZ_mm: 1; Value2: 0.1W; SizeArea_mm2: 1.28; AEC Qualified: N; VDC_V: 75V; AEC Category: Q200; SizeAreaWB_mm2: 4.68
R65 = CMP-0026455-2: RES, 576 k, 1%, 0.063 W, AEC-Q200 Grade 0, 0402; Manufacturer: Vishay-Dale; Power_W: 63mW; TempCo: 100 ppm/C; Value: 576k; EIA_Code: E96; SizeX_mm: 1; SizeY_mm: 0.5; SizeZ_mm: 0.6; Value2: 0.063W; AEC Qualified: Y; VDC_V: 50V; AEC Category: Q200; AEC Grade: 0
R66 = CMP-0026543-2: RES, 75.0 k, 1%, 0.063 W, AEC-Q200 Grade 0, 0402; Manufacturer: Vishay-Dale; Power_W: 63mW; TempCo: 100 ppm/C; Value_Code: 75k0; Value: 75.0k; EIA_Code: E96; Res_ohm: 75k; SizeX_mm: 1; SizeY_mm: 0.5; SizeZ_mm: 0.6; Value2: 0.063W; AEC Qualified: Y; VDC_V: 50V; AEC Category: Q200; AEC Grade: 0
R67 = CMP-0026859-2: RES, 1.0 M, 5%, 0.063 W, AEC-Q200 Grade 0, 0402; Manufacturer: Vishay-Dale; Power_W: 63mW; TempCo: 200 ppm/C; Value_Code: 1M00; Value: 1.0Meg; EIA_Code: E24; Res_ohm: 1M; SizeX_mm: 1; SizeY_mm: 0.5; SizeZ_mm: 0.6; Value2: 0.063W; AEC Qualified: Y; VDC_V: 50V; AEC Category: Q200; AEC Grade: 0
R69 = CMP-0023253-5: RES, 6.80 k, 1%, 0.1 W, 0603; Manufacturer: Yageo; Power_W: 100mW; TempCo: 100 ppm/C; Value_Code: 6k80; Value: 6.80k; Res_ohm: 6.8k; SizeX_mm: 1.6; SizeY_mm: 0.8; SizeZ_mm: 1; Value2: 0.1W; SizeArea_mm2: 1.28; AEC Qualified: N; VDC_V: 75V; AEC Category: Q200; SizeAreaWB_mm2: 4.68
R71 = CMP-0078244-2: RES, 30.0 k, 1%, 0.063 W, AEC-Q200 Grade 0, 0402; Manufacturer: Vishay-Dale; Power_W: 63mW; Green_Lifecycle: Active; TempCo: 100 ppm/C; Value_Code: 30k0; Green_REACh: Passed; Value: 30.0k; Res_ohm: 30k; SizeX_mm: 1; SizeY_mm: 0.5; SizeZ_mm: 0.6; Value2: 0.063W; AEC Qualified: Y; VDC_V: 50V; AEC Grade: 0; AEC Category: Q200
RT2 = CMP-0002523-3: Thermistor NTC, 47k ohm, 5%, 0603; Manufacturer: MuRata; TaMax_C: 125°C; SizeX_mm: 1.6; SizeY_mm: 0.8; TaMin_C: -40°C; Power_W: 100mW; SizeZ_mm: 1; SizeArea_mm2: 1.28; SizeAreaWB_mm2: 4.68; U/M: EA
T3 = CMP-0087465-1: Lm=200uH, Llk=5uH / P:S1:S2:A = 40:10:10:15; Manufacturer: Renco Electronics; AEC Qualified: No; SizeZ_mm: 0.66inch; DCR_ohm: 0.1; Ind_H: 110µH; Ns1toNp: 2.5:0.5:1:0.5:1
U9 = CMP-0860377-2: 4-A/6-A, Single-Channel Reinforced Isolation Gate Driver with High Noise Immunity, DWV0008A (SOIC-8); Manufacturer: Texas Instruments; SizeX_mm: 11.5; SizeArea_mm2: 67.275; SizeAreaWB_mm2: 105.975; CompType: IC; SizeZ_mm: 2.8; SizeY_mm: 5.85; AEC Category: Q200; AEC Qualified: N
U10 = CMP-0086087-1: UCC28781RTW, RTW0024B (WQFN-24); Manufacturer: Texas Instruments; SizeY_mm: 4; SizeZ_mm: 0.8; AEC Category: Q200; SizeArea_mm2: 16; CompType: IC; AEC Qualified: N; SizeAreaWB_mm2: 25
U11 = CMP-0087394-2: Optoisolator Transistor Output 5000Vrms 1 Channel 6-SO; Manufacturer: Toshiba; CTR (Max): 300%; CTR (Min): 100%; SizeZ_mm: 2.3mm
U12 = CMP-0066199-1: 2.5V Low Iq Adjustable Precision Shunt Regulator, DBZ0003A (SOT-23-3); Manufacturer: Texas Instruments; SizeArea_mm2: 7.5; SizeAreaWB_mm2: 14.0; SizeX_mm: 2.5; SizeY_mm: 3.0; SizeZ_mm: 1.12; CompType: IC; U/M: EA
